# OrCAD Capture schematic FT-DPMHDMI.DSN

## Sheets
1 INDEX: title: 01-INDEX; rev: 1.0
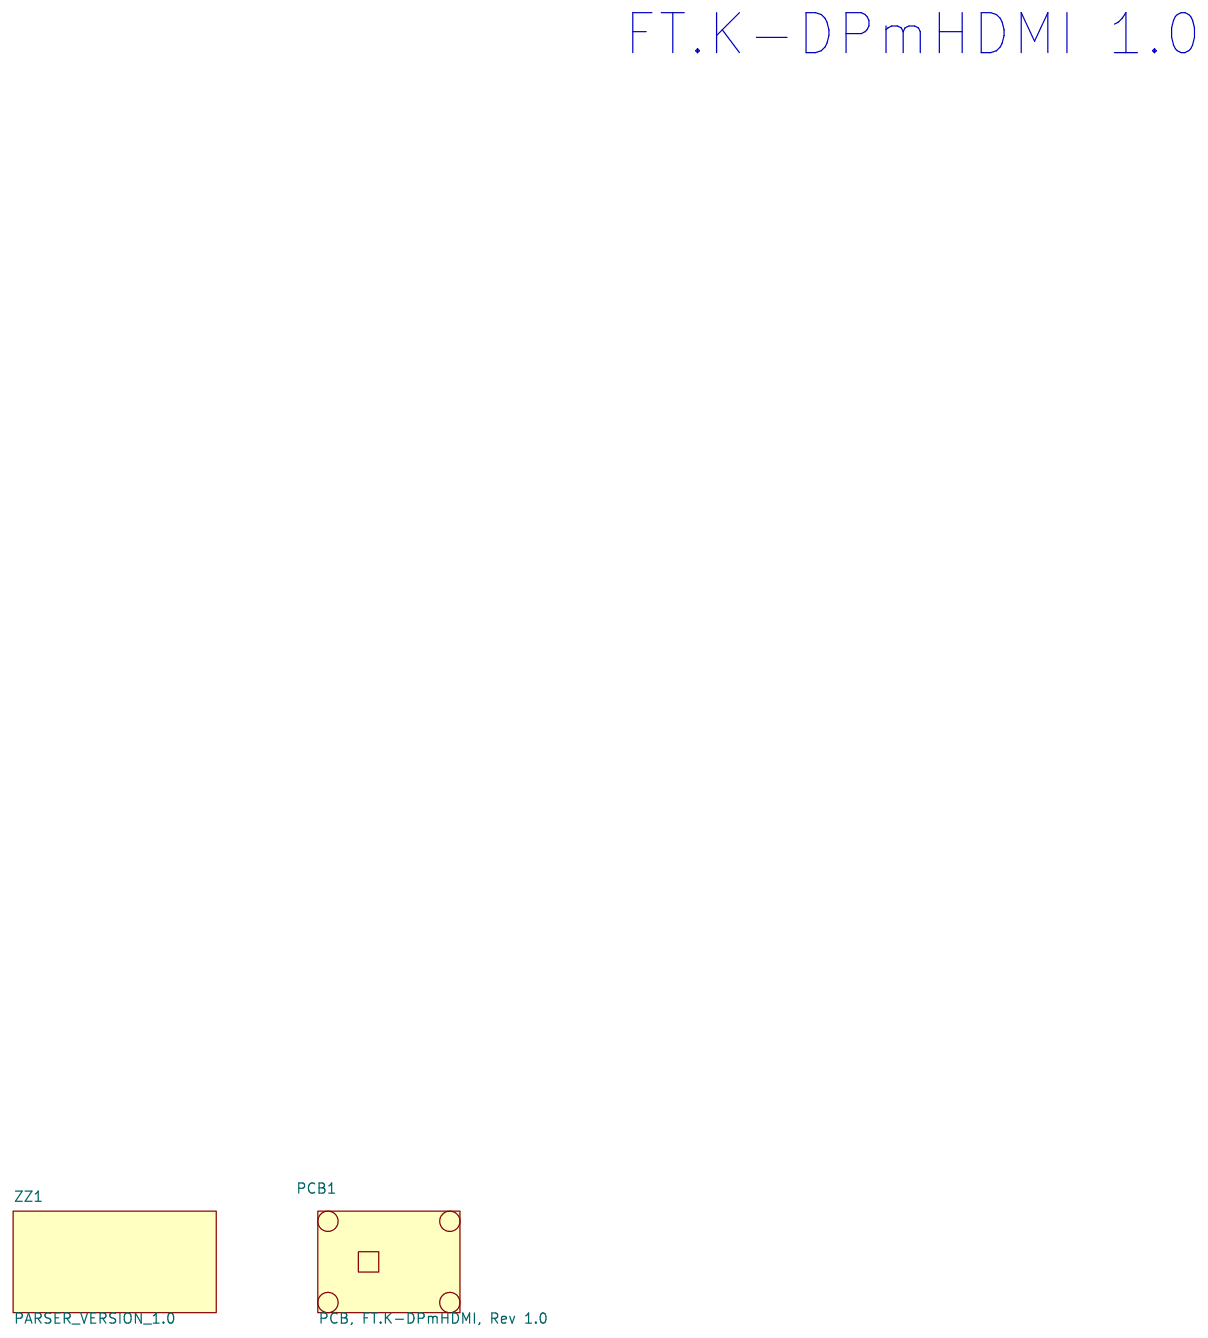
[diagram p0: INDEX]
2 TRIP: size A; title: 02-TRIP
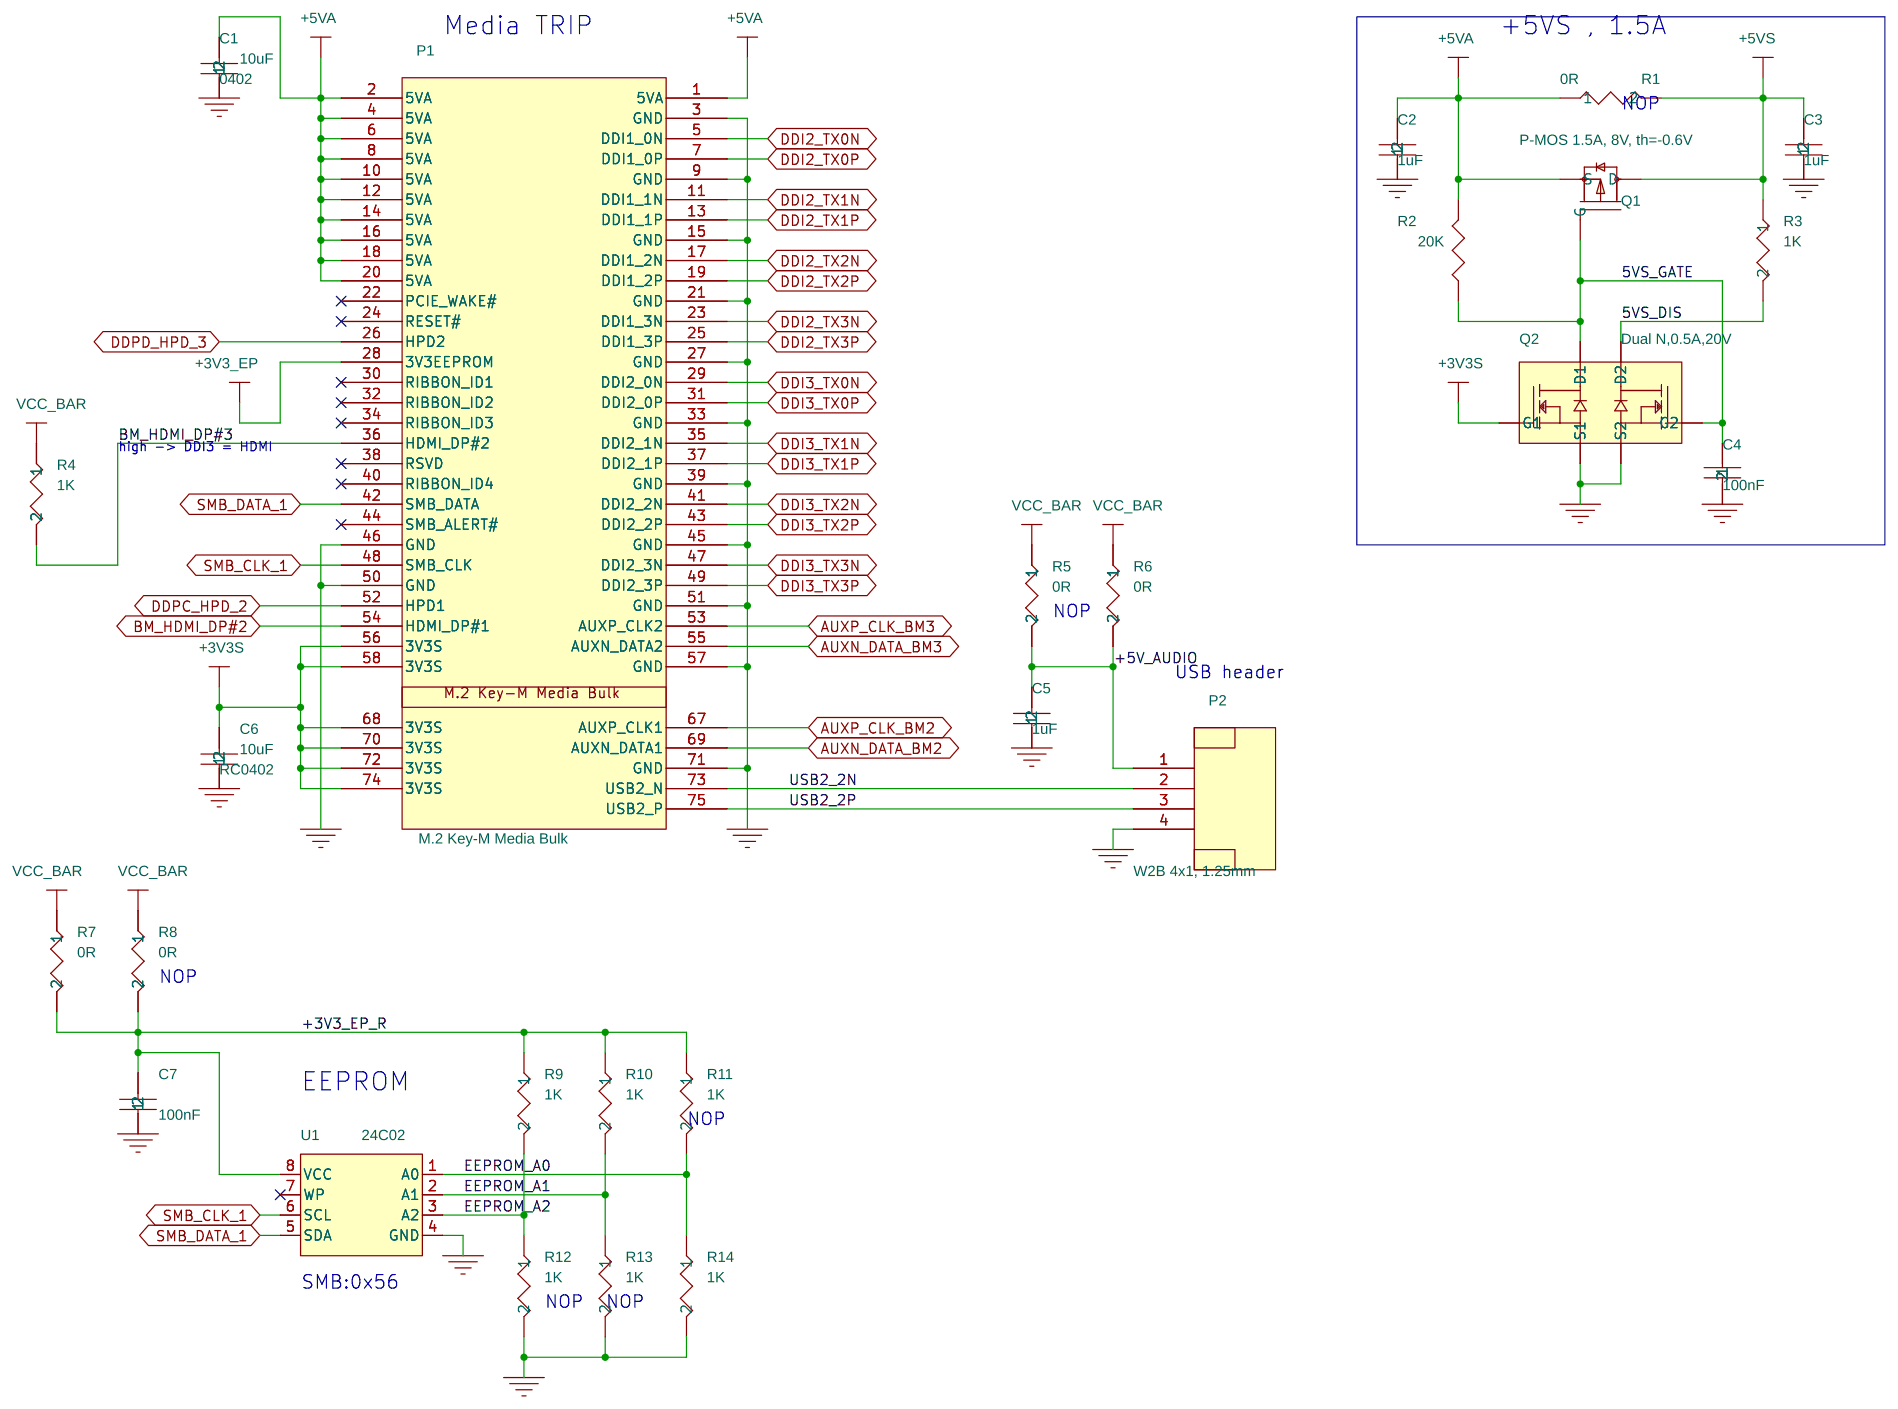
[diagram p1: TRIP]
3 mDP/HDMI: size A3; title: 03-DP/HDMI
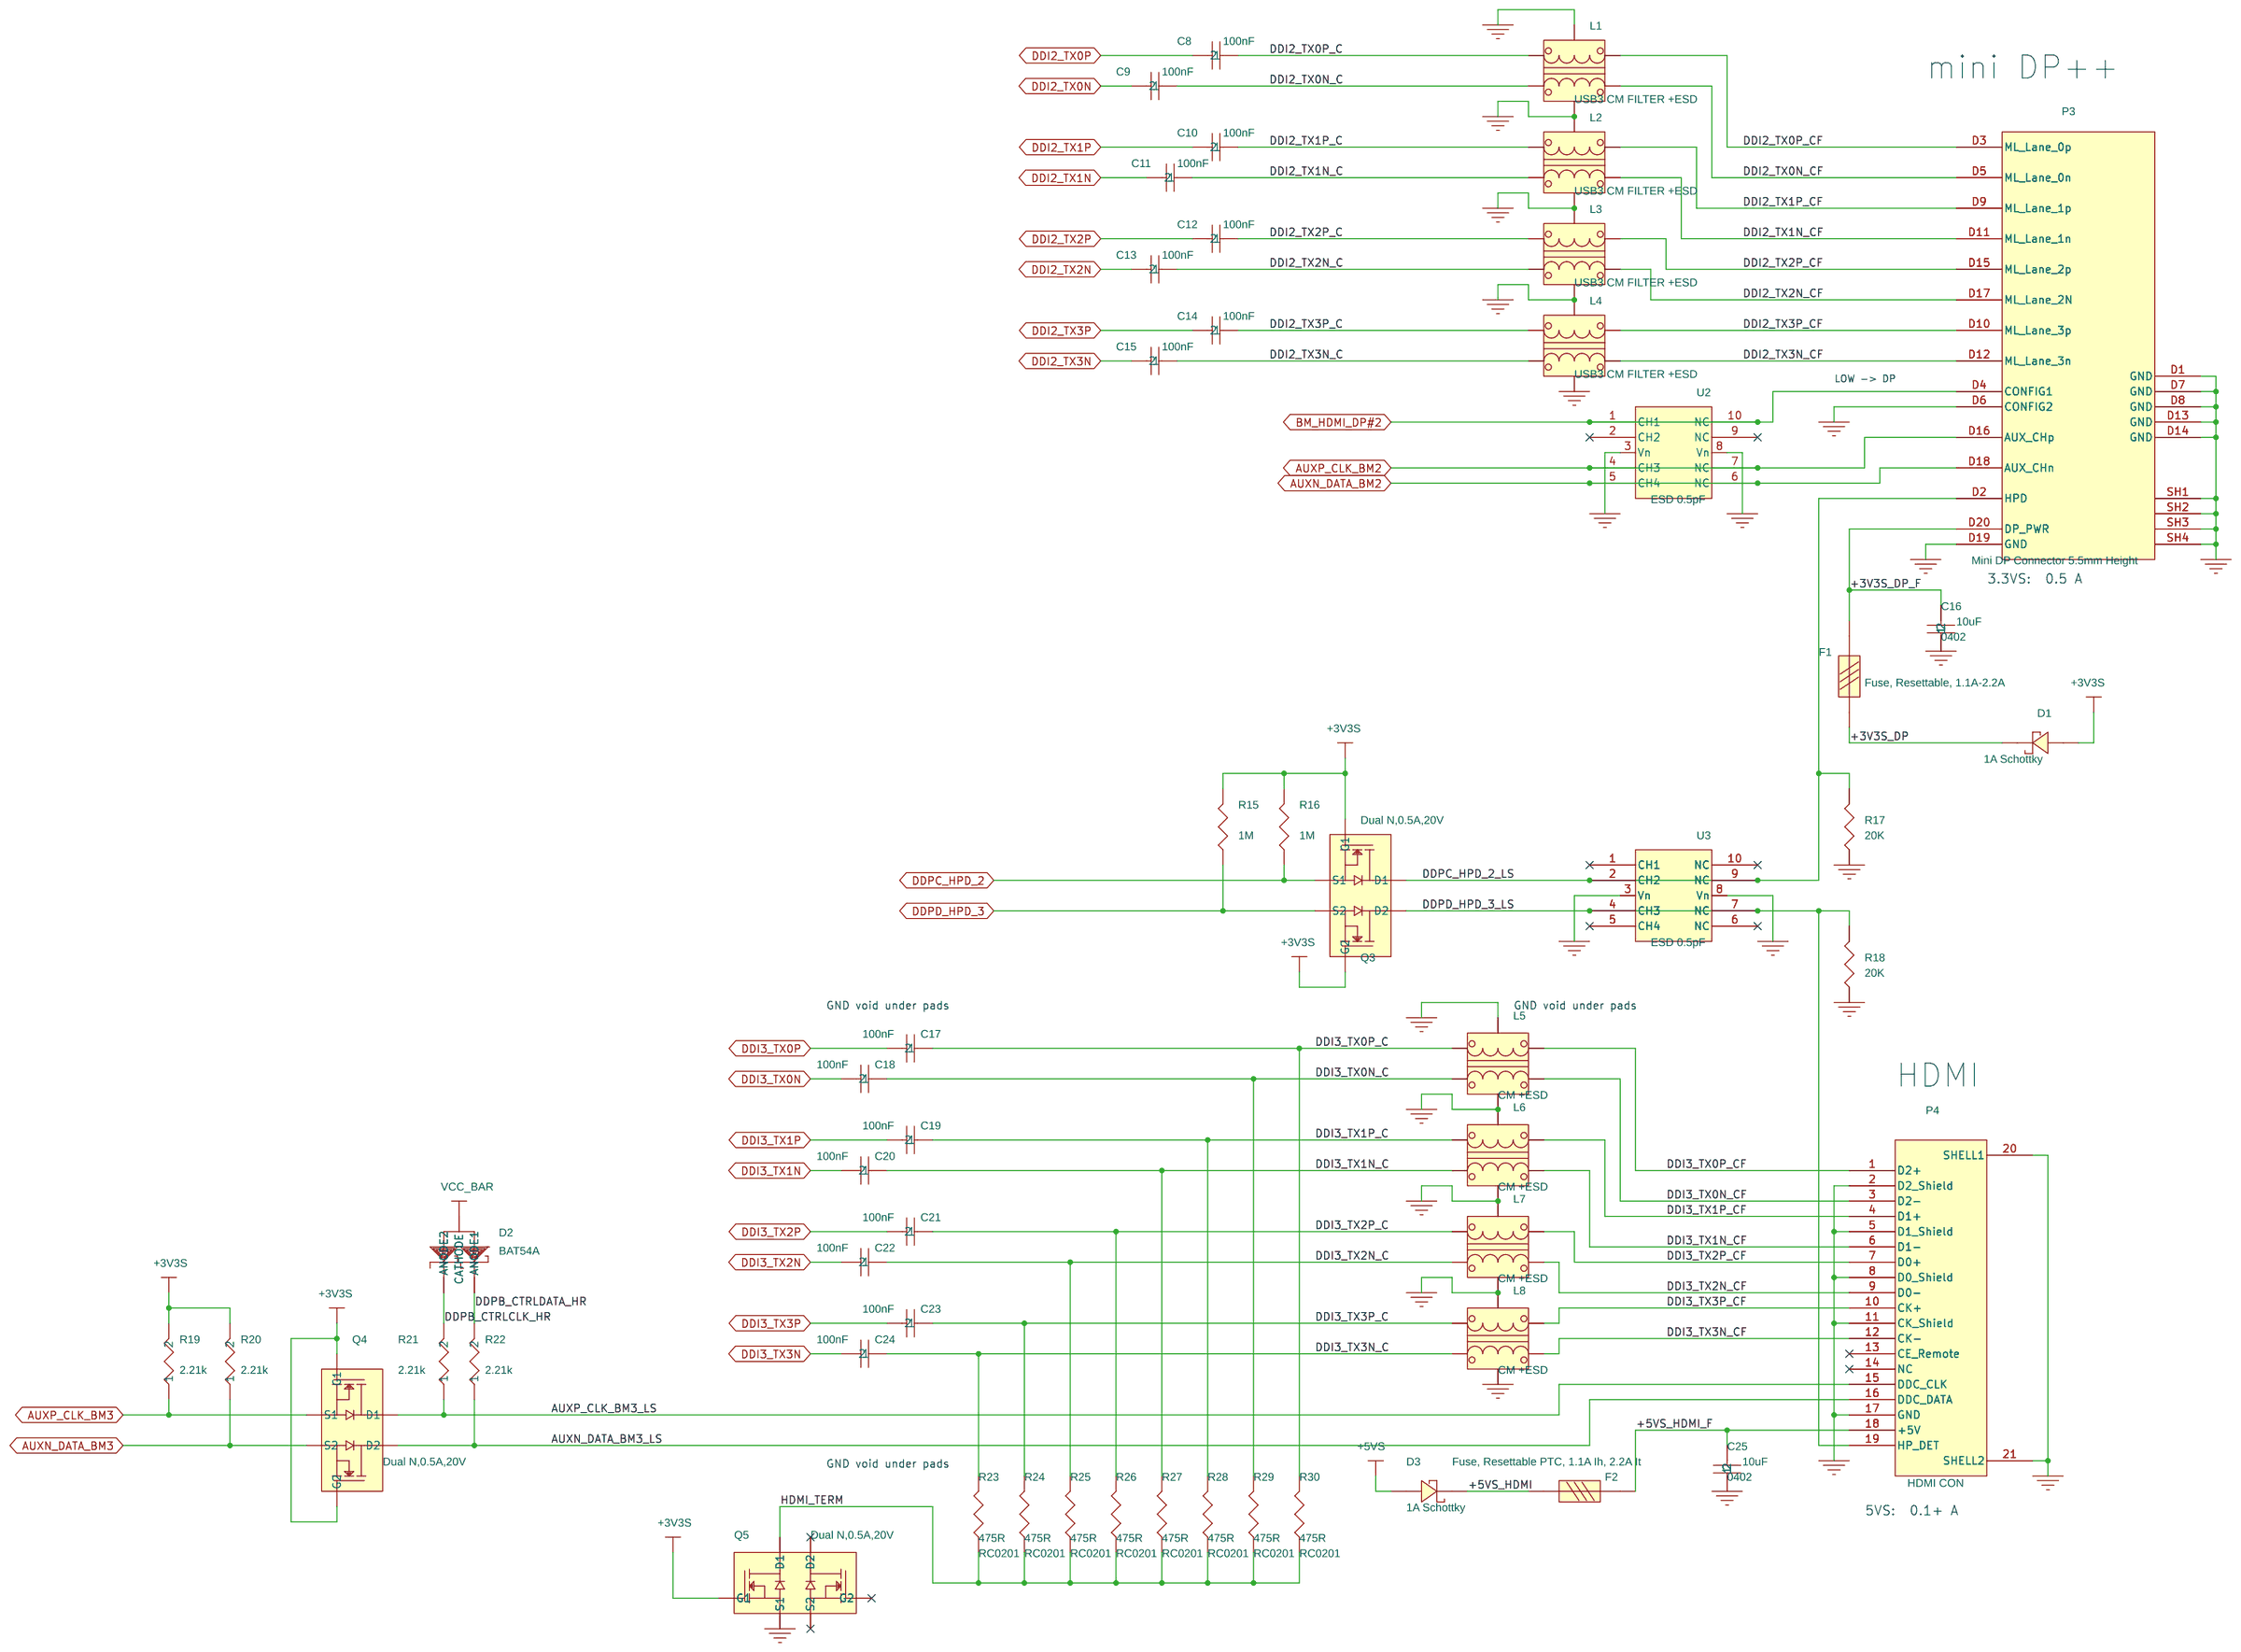
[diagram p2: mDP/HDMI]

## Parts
sheet INDEX
PCB1  PCB, FT.K-DPmHDMI, Rev 1.0
ZZ1  PARSER_VERSION_1.0
sheet mDP/HDMI
C8  100nF  [RC0402]
C9  100nF  [RC0402]
C10  100nF  [RC0402]
C11  100nF  [RC0402]
C12  100nF  [RC0402]
C13  100nF  [RC0402]
C14  100nF  [RC0402]
C15  100nF  [RC0402]
C16  10uF  [0402]
C17  100nF  [RC0402]
C18  100nF  [RC0402]
C19  100nF  [RC0402]
C20  100nF  [RC0402]
C21  100nF  [RC0402]
C22  100nF  [RC0402]
C23  100nF  [RC0402]
C24  100nF  [RC0402]
C25  10uF  [0402]
D1  1A Schottky  [SOD-123]
D2  BAT54A  [SOT23]
D3  1A Schottky  [SOD-123]
F1  Fuse, Resettable, 1.1A-2.2A  [FUSE-1206]
F2  Fuse, Resettable PTC, 1.1A Ih, 2.2A It  [FUSE-1206]
L1  USB3 CM FILTER +ESD  [EMI1012-ESD]
L2  USB3 CM FILTER +ESD  [EMI1012-ESD]
L3  USB3 CM FILTER +ESD  [EMI1012-ESD]
L4  USB3 CM FILTER +ESD  [EMI1012-ESD]
L5  CM +ESD  [EMI1012-ESD]
L6  CM +ESD  [EMI1012-ESD]
L7  CM +ESD  [EMI1012-ESD]
L8  CM +ESD  [EMI1012-ESD]
P3  Mini DP Connector 5.5mm Height  [MDP-F-RA-SM+TH]
P4  HDMI CON  [HDMI-A19-RASM]
Q3  Dual N,0.5A,20V  [SOT-563-6]
Q4  Dual N,0.5A,20V  [SOT-563-6]
Q5  Dual N,0.5A,20V  [SOT-563-6]
R15  1M  [RC0402]
R16  1M  [RC0402]
R17  20K  [RC0402]
R18  20K  [RC0402]
R19  2.21k  [RC0402]
R20  2.21k  [RC0402]
R21  2.21k  [RC0402]
R22  2.21k  [RC0402]
R23  475R  [RC0201]
R24  475R  [RC0201]
R25  475R  [RC0201]
R26  475R  [RC0201]
R27  475R  [RC0201]
R28  475R  [RC0201]
R29  475R  [RC0201]
R30  475R  [RC0201]
U2  ESD 0.5pF  [DFN-X2510D-10]
U3  ESD 0.5pF  [DFN-X2510D-10]
sheet TRIP
C1  10uF  [0402]
C2  1uF  [RC0402]
C3  1uF  [RC0402]
C4  100nF  [RC0402]
C5  1uF  [RC0402]
C6  10uF  [RC0402]
C7  100nF  [RC0402]
P1  M.2 Key-M Media Bulk  [NGFF67P8HMkeySM]
P2  W2B 4x1, 1.25mm  [1x4W2B1_25RASM]
Q1  P-MOS 1.5A, 8V, th=-0.6V  [SOT23]
Q2  Dual N,0.5A,20V  [SOT-563-6]
R1  0R  [RC0402]
R2  20K  [RC0402]
R3  1K  [RC0402]
R4  1K  [RC0402]
R5  0R  [RC0402]
R6  0R  [RC0402]
R7  0R  [RC0402]
R8  0R  [RC0402]
R9  1K  [RC0402]
R10  1K  [RC0402]
R11  1K  [RC0402]
R12  1K  [RC0402]
R13  1K  [RC0402]
R14  1K  [RC0402]
U1  24C02  [MO-229VCED-2]

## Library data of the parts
PCB1 = SBC-iHSW_Rev_1.0: CLABCONF0: FT.K-DPmHDMI; P/N: 188C03460
ZZ1 = PARSER_VERSION_1.0: CLABCONF0: FT.K-DPmHDMI
C8 = 15pF,_50V,_NPO,_5%,_0402_6: CLABCONF0: FT.K-DPmHDMI; P/N: 151B10400S
C9 = 15pF,_50V,_NPO,_5%,_0402_5: CLABCONF0: FT.K-DPmHDMI; P/N: 151B10400S
C10 = 15pF,_50V,_NPO,_5%,_0402_4: CLABCONF0: FT.K-DPmHDMI; P/N: 151B10400S
C11 = 15pF,_50V,_NPO,_5%,_0402_7: CLABCONF0: FT.K-DPmHDMI; P/N: 151B10400S
C12 = 15pF,_50V,_NPO,_5%,_0402_2: CLABCONF0: FT.K-DPmHDMI; P/N: 151B10400S
C13 = 15pF,_50V,_NPO,_5%,_0402_1: CLABCONF0: FT.K-DPmHDMI; P/N: 151B10400S
C14 = 15pF,_50V,_NPO,_5%,_0402_3: CLABCONF0: FT.K-DPmHDMI; P/N: 151B10400S
C7 C15 = 15pF,_50V,_NPO,_5%,_0402: CLABCONF0: FT.K-DPmHDMI; P/N: 151B10400S
C16 = 100nF,_10V,_X7R,_10%,_0402_9: CLABCONF0: FT.K-DPmHDMI; P/N: 151B10600S
C4 C17 = 100nF,_10V,_X7R,_10%,_0402_5: CLABCONF0: FT.K-DPmHDMI; P/N: 151B10400S
C18 = 100nF,_10V,_X7R,_10%,_0402_7: CLABCONF0: FT.K-DPmHDMI; P/N: 151B10400S
C19 = 100nF,_10V,_X7R,_10%,_0402_1: CLABCONF0: FT.K-DPmHDMI; P/N: 151B10400S
C20 = 100nF,_10V,_X7R,_10%,_0402_6: CLABCONF0: FT.K-DPmHDMI; P/N: 151B10400S
C21 = 100nF,_10V,_X7R,_10%,_0402_4: CLABCONF0: FT.K-DPmHDMI; P/N: 151B10400S
C22 = 100nF,_10V,_X7R,_10%,_0402: CLABCONF0: FT.K-DPmHDMI; P/N: 151B10400S
C23 = 100nF,_10V,_X7R,_10%,_0402_2: CLABCONF0: FT.K-DPmHDMI; P/N: 151B10400S
C24 = 100nF,_10V,_X7R,_10%,_0402_8: CLABCONF0: FT.K-DPmHDMI; P/N: 151B10400S
C25 = 100nF,_10V,_X7R,_10%,_0402_3: CLABCONF0: FT.K-DPmHDMI; P/N: 151B10600S
D1 D3 = 1A_Schottky_Barrier_Rectifier: CLABCONF0: FT.K-DPmHDMI
D2 = BAT54A: CLABCONF0: FT.K-DPmHDMI; P/N: 130E05403S
F1 F2 = Fuse,_1.1_A_Ih,_2.2A_It: CLABCONF0: FT.K-DPmHDMI
L1-L8 = USB3_CHOKE_+_ESD_FILTER: CLABCONF0: FT.K-DPmHDMI; P/N: 142D11801S
P3 = Mini_DP_connector_2: CLABCONF0: FT.K-DPmHDMI; P/N: 180K02002S
P4 = HDMI_Connector: CLABCONF0: FT.K-DPmHDMI
Q2-Q5 = DUAL_N-MOSFET,_0.5A_20V: CLABCONF0: FT.K-DPmHDMI
R15 R16 = RESISTOR: CLABCONF0: FT.K-DPmHDMI; P/N: 161C10045S
R2 R17 R18 = RESISTOR: CLABCONF0: FT.K-DPmHDMI; P/N: 161C20021S
R19 = 1M_,5%,_0402_1: CLABCONF0: FT.K-DPmHDMI; P/N: 161C22111S
R20 = 1M_,5%,_0402: CLABCONF0: FT.K-DPmHDMI; P/N: 161C22111S
R21 = 1M_,5%,_0402_2: CLABCONF0: FT.K-DPmHDMI; P/N: 161C22111S
R22 = 1M_,5%,_0402_3: CLABCONF0: FT.K-DPmHDMI; P/N: 161C22111S
R23-R30 = RESISTOR: CLABCONF0: FT.K-DPmHDMI; P/N: 161B47501S
U2 U3 = IC,ESD_Diode,0.25pF_,x4: CLABCONF0: FT.K-DPmHDMI; P/N: 132D10020S
C1 = 100nF,_10V,_X7R,_10%,_0402_1: CLABCONF0: FT.K-DPmHDMI; P/N: 151B10600S
C2 = 100nF,_10V,_X7R,_10%,_0402_3: CLABCONF0: FT.K-DPmHDMI; P/N: 151C10500S
C3 = 100nF,_10V,_X7R,_10%,_0402_2: CLABCONF0: FT.K-DPmHDMI; P/N: 151C10500S
C5 = 100nF,_10V,_X7R,_10%,_0402: CLABCONF0: FT.K-DPmHDMI; P/N: 151C10500S
C6 = 100nF,_10V,_X7R,_10%,_0402_4: CLABCONF0: FT.K-DPmHDMI; P/N: 151B10600S
P1 = M.2_Key-M_Media_Bulk: CLABCONF0: FT.K-DPmHDMI; P/N: 182K06700S
P2 = W2B_4x1_HDR,_1.25mm: CLABCONF0: FT.K-DPmHDMI; P/N: 182E00401S
Q1 = P-MOSFET,3A,20V,110mOhm@-1.8V: CLABCONF0: FT.K-DPmHDMI; P/N: 131D21010S
R1 = 348R,1%,0402,1_16W_10: CLABCONF0: NOP; P/N: 161C00005S
R3 = 348R,1%,0402,1_16W: CLABCONF0: FT.K-DPmHDMI; P/N: 161C10011S
R4 = 348R,1%,0402,1_16W_9: CLABCONF0: FT.K-DPmHDMI; P/N: 161C10011S
R5 = 348R,1%,0402,1_16W_6: CLABCONF0: NOP; P/N: 161C00005S
R6 = 348R,1%,0402,1_16W_5: CLABCONF0: FT.K-DPmHDMI; P/N: 161C00005S
R7 = 348R,1%,0402,1_16W_3: CLABCONF0: FT.K-DPmHDMI; P/N: 161C00005S
R8 = 348R,1%,0402,1_16W_2: CLABCONF0: NOP; P/N: 161C00005S
R9 = 348R,1%,0402,1_16W_4: CLABCONF0: FT.K-DPmHDMI; P/N: 161C10011S
R10 = 348R,1%,0402,1_16W_11: CLABCONF0: FT.K-DPmHDMI; P/N: 161C10011S
R11 = 348R,1%,0402,1_16W_8: CLABCONF0: NOP; P/N: 161C10011S
R12 = 348R,1%,0402,1_16W_1: CLABCONF0: NOP; P/N: 161C10011S
R13 = 348R,1%,0402,1_16W_7: CLABCONF0: NOP; P/N: 161C10011S
R14 = 348R,1%,0402,1_16W_12: CLABCONF0: FT.K-DPmHDMI; P/N: 161C10011S
U1 = 24C02,_serial_EE,_2KB,_I2C: CLABCONF0: FT.K-DPmHDMI; P/N: 111S30801S

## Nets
5VS_DIS: Q2.3(D2) R3.2
5VS_GATE: C4.1 Q1.1(G) Q2.5(G2) Q2.6(D1) R2.1
+3V3_EP: P1.28(3V3EEPROM) R7.1
+3V3_EP_R: C7.2 R7.2 R8.2 R9.1 R10.1 R11.1 U1.8(VCC)
+3V3S: C6.2 D1.2(ANODE) P1.56(3V3S) P1.58(3V3S) P1.68(3V3S) P1.70(3V3S) P1.72(3V3S) P1.74(3V3S) Q2.2(G1) Q3.2(G1) Q3.5(G2) Q4.2(G1) Q4.5(G2) Q5.2(G1) R4.1 R8.1 R15.2 R16.2 R19.2 R20.2
+3V3S_DP: D1.1(CATHODE) F1.2
+3V3S_DP_F: C16.2 F1.1 P3.D20(DP_PWR)
+5V_AUDIO: C5.2 P2.1 R5.2 R6.2
+5VA: C1.2 C2.2 P1.1(5VA) P1.2(5VA) P1.4(5VA) P1.6(5VA) P1.8(5VA) P1.10(5VA) P1.12(5VA) P1.14(5VA) P1.16(5VA) P1.18(5VA) P1.20(5VA) Q1.2(S) R1.1 R2.2 R5.1
+5VS: C3.2 D2.3(CATHODE) D3.2(ANODE) Q1.3(D) R1.2 R3.1 R6.1
+5VS_HDMI: D3.1(CATHODE) F2.2
+5VS_HDMI_F: C25.2 F2.1 P4.18(+5V)
GND: C1.1 C2.1 C3.1 C4.2 C5.1 C6.1 C7.1 C16.1 C25.1 L1.5 L1.6 L2.5 L2.6 L3.5 L3.6 L4.5 L4.6 L5.5 L5.6 L6.5 L6.6 L7.5 L7.6 L8.5 L8.6 P1.3(GND) P1.9(GND) P1.15(GND) P1.21(GND) P1.27(GND) P1.33(GND) P1.39(GND) P1.45(GND) P1.46(GND) P1.50(GND) P1.51(GND) P1.57(GND) P1.71(GND) P2.4 P3.D1(GND) P3.D6(CONFIG2) P3.D7(GND) P3.D8(GND) P3.D13(GND) P3.D14(GND) P3.D19(GND) P3.SH1 P3.SH2 P3.SH3 P3.SH4 P4.2(D2_Shield) P4.5(D1_Shield) P4.8(D0_Shield) P4.11(CK_Shield) P4.17(GND) P4.20(SHELL1) P4.21(SHELL2) Q2.1(S1) Q2.4(S2) Q5.1(S1) R12.2 R13.2 R14.2 R17.1 R18.1 U1.4(GND) U2.3(Vn) U2.8(Vn) U3.3(Vn) U3.8(Vn)
AUXN_DATA_BM2: P1.69(AUXN_DATA1) P3.D18(AUX_CHn) U2.5(CH4) U2.6(NC)
AUXN_DATA_BM3: P1.55(AUXN_DATA2) Q4.4(S2) R20.1
AUXN_DATA_BM3_LS: P4.16(DDC_DATA) Q4.3(D2) R22.1
AUXP_CLK_BM2: P1.67(AUXP_CLK1) P3.D16(AUX_CHp) U2.4(CH3) U2.7(NC)
AUXP_CLK_BM3: P1.53(AUXP_CLK2) Q4.1(S1) R19.1
AUXP_CLK_BM3_LS: P4.15(DDC_CLK) Q4.6(D1) R21.1
BM_HDMI_DP#2: P1.54(HDMI_DP#1) P3.D4(CONFIG1) U2.1(CH1) U2.10(NC)
BM_HDMI_DP#3: P1.36(HDMI_DP#2) R4.2
DDI2_TX0N: C9.2 P1.5(DDI1_0N)
DDI2_TX0N_C: C9.1 L1.3
DDI2_TX0N_CF: L1.2 P3.D5(ML_Lane_0n)
DDI2_TX0P: C8.2 P1.7(DDI1_0P)
DDI2_TX0P_C: C8.1 L1.4
DDI2_TX0P_CF: L1.1 P3.D3(ML_Lane_0p)
DDI2_TX1N: C11.2 P1.11(DDI1_1N)
DDI2_TX1N_C: C11.1 L2.3
DDI2_TX1N_CF: L2.2 P3.D11(ML_Lane_1n)
DDI2_TX1P: C10.2 P1.13(DDI1_1P)
DDI2_TX1P_C: C10.1 L2.4
DDI2_TX1P_CF: L2.1 P3.D9(ML_Lane_1p)
DDI2_TX2N: C13.2 P1.17(DDI1_2N)
DDI2_TX2N_C: C13.1 L3.3
DDI2_TX2N_CF: L3.2 P3.D17(ML_Lane_2N)
DDI2_TX2P: C12.2 P1.19(DDI1_2P)
DDI2_TX2P_C: C12.1 L3.4
DDI2_TX2P_CF: L3.1 P3.D15(ML_Lane_2p)
DDI2_TX3N: C15.2 P1.23(DDI1_3N)
DDI2_TX3N_C: C15.1 L4.3
DDI2_TX3N_CF: L4.2 P3.D12(ML_Lane_3n)
DDI2_TX3P: C14.2 P1.25(DDI1_3P)
DDI2_TX3P_C: C14.1 L4.4
DDI2_TX3P_CF: L4.1 P3.D10(ML_Lane_3p)
DDI3_TX0N: C18.2 P1.29(DDI2_0N)
DDI3_TX0N_C: C18.1 L5.3 R29.2
DDI3_TX0N_CF: L5.2 P4.3(D2-)
DDI3_TX0P: C17.2 P1.31(DDI2_0P)
DDI3_TX0P_C: C17.1 L5.4 R30.2
DDI3_TX0P_CF: L5.1 P4.1(D2+)
DDI3_TX1N: C20.2 P1.35(DDI2_1N)
DDI3_TX1N_C: C20.1 L6.3 R27.2
DDI3_TX1N_CF: L6.2 P4.6(D1-)
DDI3_TX1P: C19.2 P1.37(DDI2_1P)
DDI3_TX1P_C: C19.1 L6.4 R28.2
DDI3_TX1P_CF: L6.1 P4.4(D1+)
DDI3_TX2N: C22.2 P1.41(DDI2_2N)
DDI3_TX2N_C: C22.1 L7.3 R25.2
DDI3_TX2N_CF: L7.2 P4.9(D0-)
DDI3_TX2P: C21.2 P1.43(DDI2_2P)
DDI3_TX2P_C: C21.1 L7.4 R26.2
DDI3_TX2P_CF: L7.1 P4.7(D0+)
DDI3_TX3N: C24.2 P1.47(DDI2_3N)
DDI3_TX3N_C: C24.1 L8.3 R23.2
DDI3_TX3N_CF: L8.2 P4.12(CK-)
DDI3_TX3P: C23.2 P1.49(DDI2_3P)
DDI3_TX3P_C: C23.1 L8.4 R24.2
DDI3_TX3P_CF: L8.1 P4.10(CK+)
DDPB_CTRLCLK_HR: D2.2(ANODE2) R21.2
DDPB_CTRLDATA_HR: D2.1(ANODE1) R22.2
DDPC_HPD_2: P1.52(HPD1) Q3.1(S1) R16.1
DDPC_HPD_2_LS: P3.D2(HPD) Q3.6(D1) R17.2 U3.2(CH2) U3.9(NC)
DDPD_HPD_3: P1.26(HPD2) Q3.4(S2) R15.1
DDPD_HPD_3_LS: P4.19(HP_DET) Q3.3(D2) R18.2 U3.4(CH3) U3.7(NC)
EEPROM_A0: R11.2 R14.1 U1.1(A0)
EEPROM_A1: R10.2 R13.1 U1.2(A1)
EEPROM_A2: R9.2 R12.1 U1.3(A2)
HDMI_TERM: Q5.6(D1) R23.1 R24.1 R25.1 R26.1 R27.1 R28.1 R29.1 R30.1
SMB_CLK_1: P1.48(SMB_CLK) U1.6(SCL)
SMB_DATA_1: P1.42(SMB_DATA) U1.5(SDA)
USB2_2N: P1.73(USB2_N) P2.2
USB2_2P: P1.75(USB2_P) P2.3

Not connected (* = marked no-connect by the designer): P1 22(PCIE_WAKE#)* 24(RESET#)* 30(RIBBON_ID1)* 32(RIBBON_ID2)* 34(RIBBON_ID3)* 38(RSVD)* 40(RIBBON_ID4)* 44(SMB_ALERT#)*; P4 13(CE_Remote)* 14(NC)*; Q5 3(D2)* 4(S2)* 5(G2)*; U1 7(WP)*; U2 2(CH2)* 9(NC)*; U3 1(CH1)* 5(CH4)* 6(NC)* 10(NC)*

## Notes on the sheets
sheet 1
- FT.K-DPmHDMI 1.0
sheet 2
- Media TRIP
- +5VS , 1.5A
- NOP
- high -> DDI3 = HDMI
- NOP
- USB header
- NOP
- EEPROM
- NOP
- SMB:0x56
- NOP
- NOP
sheet 3
- mini DP++
- LOW -> DP
- 3.3VS:  0.5 A
- GND void under pads
- GND void under pads
- HDMI
- GND void under pads
- 5VS:  0.1+ A
